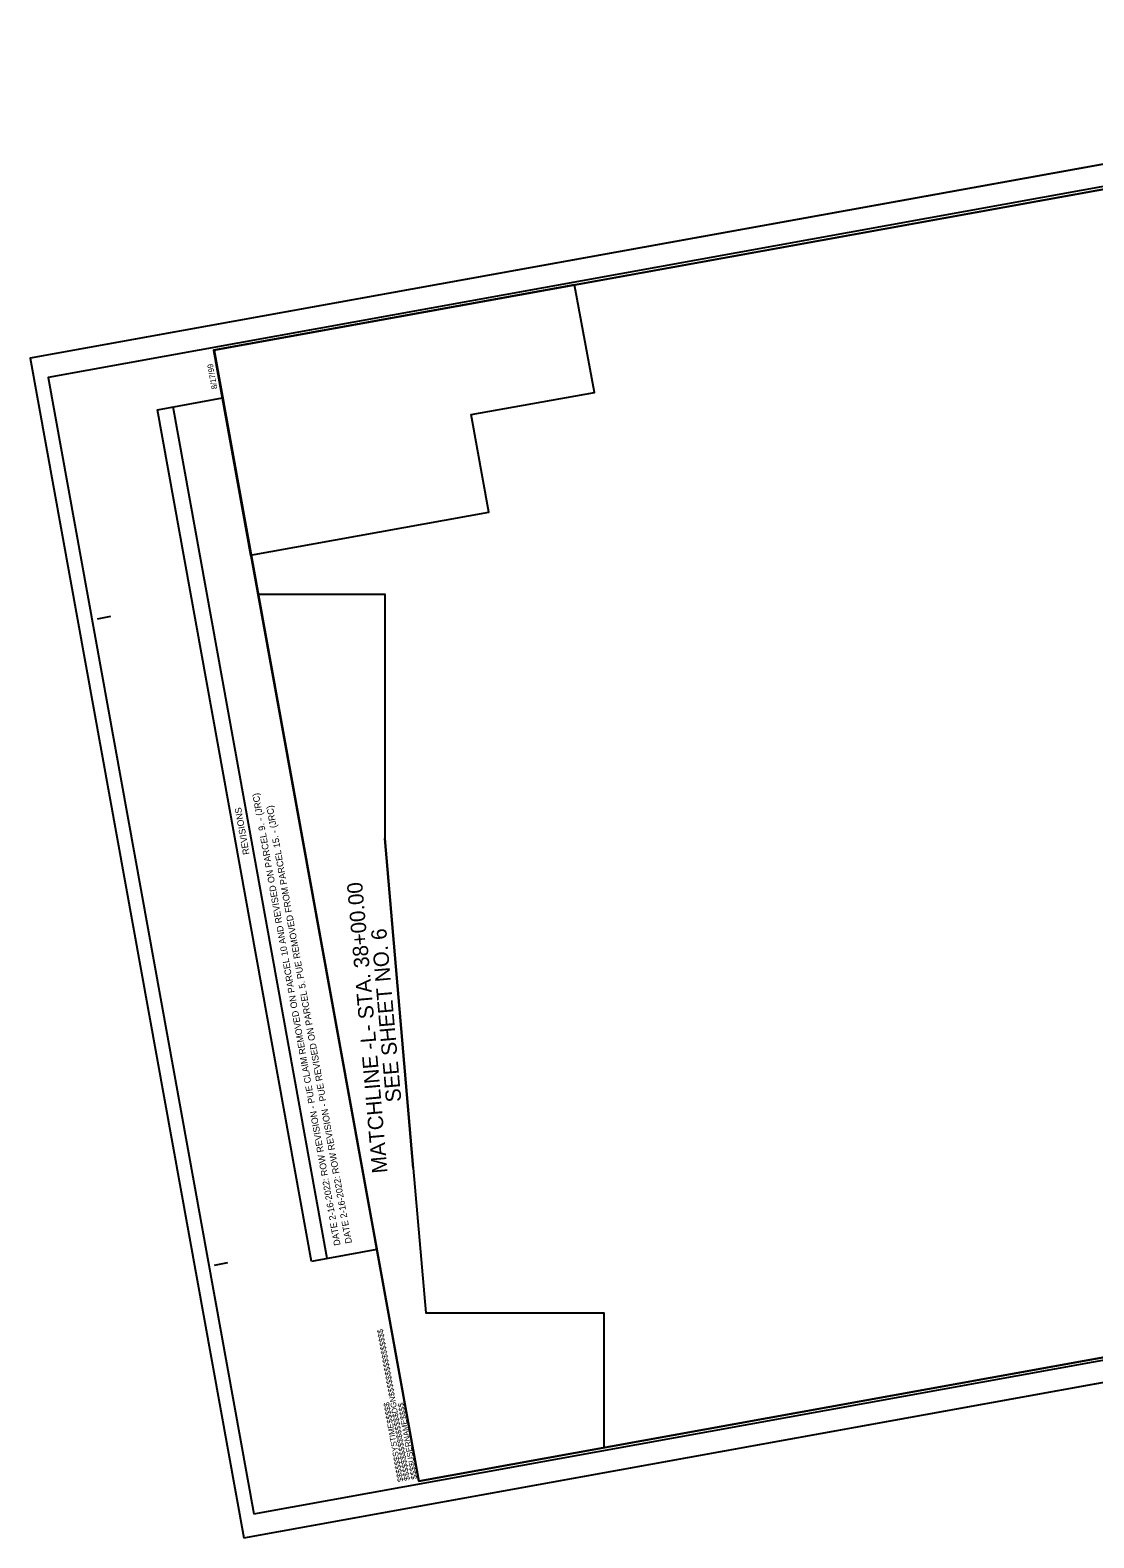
# Model space of a CAD drawing. Extents: x 1620188 to 1622130, y 897586 to 898964.
# Drawn here: x 1620188 to 1621159, y 897586 to 898964 of the extents above; entities that cross this region are included whole.
import ezdxf

# ---------------------------------------------------------------- set-up
doc = ezdxf.new("R2010")
doc.units = 0
for name, color, linetype in [('Matchline', 7, 'Continuous'), ('Matchline Text', 7, 'Continuous'), ('Sheet Block Revision CELL', 7, 'Continuous'), ('Sheet Cutting Line CELL', 7, 'Continuous'), ('Sheet Layout Plan Border', 7, 'Continuous'), ('Sheet Plan CELL', 7, 'Continuous'), ('Sheet Plot Border Inside CELL', 7, 'Continuous'), ('Sheet Plot Border Outside CELL', 7, 'Continuous')]:
    doc.layers.add(name, color=color, linetype=linetype)

msp = doc.modelspace()

# ---------------------------------------------------------------- linework, layer by layer
at = {"layer": 'Matchline'}
msp.add_lwpolyline([(1620537.8, 897924.1), (1620511.8, 898225.2)], dxfattribs=at)
at = {"layer": 'Sheet Block Revision CELL'}
msp.add_line((1620459.2, 897841.5), (1620318.4, 898619.5), dxfattribs=at)
msp.add_lwpolyline([(1620444.9, 897838.9), (1620304.1, 898616.9), (1620363.7, 898627.7), (1620504.5, 897849.7)], close=True, dxfattribs=at)
at = {"layer": 'Sheet Cutting Line CELL'}
for p, q in [((1621844.5, 898963.7), (1620187.9, 898663.9)), ((1620187.9, 898663.9), (1620382.9, 897586.4)), ((1620382.9, 897586.4), (1622039.5, 897886.2))]:
    msp.add_line(p, q, dxfattribs=at)
at = {"layer": 'Sheet Layout Plan Border'}
for points in [[(1620396.1, 898448.3), (1620511.7, 898448.3), (1620511.8, 898225.2), (1620537.8, 897924.1), (1620549.3, 897792), (1620711.8, 897792), (1620711.8, 897668.8), (1621290.7, 897773.5), (1621387.6, 897791.1), (1621474.2, 897806.7), (1621466.5, 897830.2), (1621752, 897906.6), (1621799.3, 897865.6), (1622018.8, 897905.3), (1621899.5, 898564.6), (1621869, 898733), (1621765.3, 898714.2), (1621672.2, 898697.4), (1621635, 898902.9), (1620355.8, 898671.4)], [(1620389.1, 898484.2), (1620606.8, 898523.2), (1620590.7, 898612.5), (1620703.3, 898632.8), (1620684.9, 898730.9), (1620355.3, 898671.3)]]:
    msp.add_lwpolyline(points, close=True, dxfattribs=at)
at = {"layer": 'Sheet Plan CELL'}
for p, q in [((1620355.8, 898671.4), (1620355.8, 898671.4)), ((1620249.3, 898426), (1620261.6, 898428.2)), ((1620356.1, 897835.6), (1620368.4, 897837.8)), ((1620542.8, 897638.2), (1620542.8, 897638.2))]:
    msp.add_line(p, q, dxfattribs=at)
for points in [[(1621831.8, 898938.5), (1620355.8, 898671.4), (1620542.8, 897638.2), (1622018.8, 897905.3)], [(1620542.8, 897638.2), (1620355.7, 898671.4), (1621634.9, 898902.9), (1621661.7, 898755.2), (1621858.5, 898790.9), (1622018.8, 897905.3)]]:
    msp.add_lwpolyline(points, close=True, dxfattribs=at)
at = {"layer": 'Sheet Plot Border Inside CELL'}
msp.add_lwpolyline([(1620392.2, 897608.4), (1622031.5, 897905.1), (1621843.7, 898943.2), (1620204.3, 898646.5)], close=True, dxfattribs=at)
at = {"layer": 'Sheet Plot Border Outside CELL'}
msp.add_lwpolyline([(1620382.9, 897586.4), (1622039.5, 897886.2), (1621844.5, 898963.7), (1620187.9, 898663.9)], close=True, dxfattribs=at)

# ---------------------------------------------------------------- texts
at = {"layer": 'Matchline Text'}
for s, p in [('MATCHLINE -L- STA. 38+00.00', (1620514.3, 897920)), ('SEE SHEET NO. 6', (1620526.9, 897985))]:
    msp.add_text(s, height=14, rotation=95.0074, dxfattribs=at).set_placement(p)
at = {"layer": 'Sheet Block Revision CELL'}
for s, p in [('DATE 2-16-2022: ROW REVISION - PUE CLAIM REMOVED ON PARCEL 10 AND REVISED ON PARCEL 9. - (JRC)', (1620471.4, 897853.9)), ('REVISIONS', (1620388.3, 898211)), ('DATE 2-16-2022: ROW REVISION - PUE REVISED ON PARCEL 5. PUE REMOVED FROM PARCEL 15. - (JRC)', (1620481.8, 897855.8))]:
    msp.add_text(s, height=6, rotation=100.2583, dxfattribs=at).set_placement(p)
at = {"layer": 'Sheet Plan CELL'}
for s, p in [('8/17/99', (1620358.9, 898636.2)), ('$$$$$$$$$$$$$$$$DGN$$$$$$$$$$$$$$$$', (1620534.8, 897639.1)), ('$$$$$$SYSTIME$$$$$', (1620528.8, 897638)), ('$$$$USERNAME$$$$', (1620541.3, 897640.3))]:
    msp.add_text(s, height=5.25, rotation=100.2583, dxfattribs=at).set_placement(p)

doc.saveas('drawing.dxf')
